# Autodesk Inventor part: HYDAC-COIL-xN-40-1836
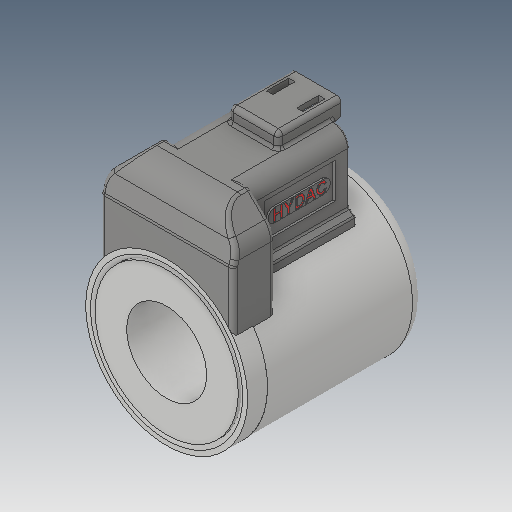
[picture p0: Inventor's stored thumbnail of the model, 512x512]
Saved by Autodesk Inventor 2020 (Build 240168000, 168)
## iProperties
DataBaseUnit: MM
Created: 2014-08
Part Number: HYDAC-COIL-xN-40-1836
Material: Generico
Description: STEP AP214
Document SubType Name: Modeling
Designer: carlo
Density: 1 g/cm^3
Appearance: Default
Sending System: SolidWorks 2014
Preprocessor: SwSTEP 2.0
Title: SW3DPS-COIL-DN-40-1836-DEFAULT.step
Author: Windows User
Revision Number: ANY
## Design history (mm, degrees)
feature "NONE"
node "Piano di lavoro1"
node "Piano di lavoro2"
node "Asse di lavoro1"
node "Solido1"
other parameters: "d0" = 0, "d1" = 0
